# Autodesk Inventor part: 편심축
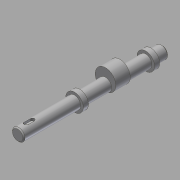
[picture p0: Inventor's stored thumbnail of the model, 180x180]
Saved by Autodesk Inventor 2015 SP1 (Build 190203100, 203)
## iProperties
Created: 2016-02
Part Number: 편심축
Material: 강철, 연강
Document SubType Name: Modeling
Designer: mduedu
Density: 1 g/cm^3
Appearance: 강철
Author: mduedu
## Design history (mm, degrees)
sketch "스케치1"
  geometry: C1 r 6 at (0, 0); 1 further point
  constraints: 1 centre point, 1 coincident
  dimensions: "d0" = 12 diameter of C1
extrude "돌출1" new body sketch "스케치1" distance "d1" = 140; taper "d2" = 0 deg
chamfer "모따기1" distance "d3" = 1; stored, may be unused: second distance "d4" = 2, angle "d5" = 45 deg
node "작업 평면1"
sketch "스케치2"
  geometry: C1 r 10 at (0, 4); C2 r 6 at (0, 0) reference; 1 further point
  constraints: 1 centre point, 1 tangent, 1 vertical alignment
  dimensions: "d7" = 20 diameter of C1
extrude "돌출2" join sketch "스케치2" stored distance "d8" = 14; taper "d9" = 0 deg
node "작업 평면2"
sketch "스케치3"
  geometry: C1 r 8.5 at (0, 0); 1 further point
  constraints: 1 centre point, 1 coincident
  dimensions: "d12" = 17 diameter of C1
extrude "돌출3" join sketch "스케치3" distance "d13" = 5; taper "d14" = 0 deg
node "작업 평면3"
sketch "스케치4"
  geometry: L1 (-5, 140)-(5, 140) reference; L2 (0, 140)-(0, 0); L3 (-2, 132)-(-2, 126); L4 (2, 126)-(2, 132); A1 r 2 centre (0, 132) between (2, 132) and (-2, 132); A2 r 2 centre (0, 126) between (-2, 126) and (2, 126)
  constraints: 6 end point, 4 point on circle, 4 tangent, 2 centre point, 2 point on line, 1 midpoint, 1 parallel, 1 perpendicular
  dimensions: "d15" = 4 distance between parallel lines of L3 L4; "d17" = 6 distance edge to line of A1 L1; "d18" = 10 dimension on A2 A1
extrude "돌출4" cut sketch "스케치4" distance "d19" = 2.5; taper "d20" = 0 deg
sketch "스케치5"
  geometry: L1 (6, 55)-(6, 139) reference; L2 (-6, 55)-(-6, 139) reference; L3 (6, 115)-(-6, 115); L4 (-5, 140)-(5, 140) reference; L5 (6, 116.5)-(4.5, 115); L6 (6, 116.5)-(6, 115); L7 (4.5, 115)-(6, 115); 1 further point
  constraints: 8 end point, 4 point on line, 2 collinear, 1 perpendicular
  dimensions: "d21" = 25 distance between parallel lines of L3 L4; "d22" = 3 diameter of L5.start L3; "d24" = 45 deg angle of L3 L5
revolve "회전1" sketch "스케치5" stored, may be unused: angle "d25" = 90 deg
sketch "스케치6"
  geometry: L1 (6, 116.5)-(4.5, 115) reference; L2 (6, 113.5)-(4.5, 115) reference; 2 further points
  constraints: 1 coincident
node "작업 평면4"
sketch "스케치7"
  geometry: C1 r 8.5 at (0, -4); 1 further point
  constraints: 1 centre point, 1 coincident
  dimensions: "d27" = 17 diameter of C1
extrude "돌출5" join sketch "스케치7" distance "d29" = 5; taper "d30" = 0 deg
node "솔리드1"
other parameters: "d6" = -48, "d11" = -11
